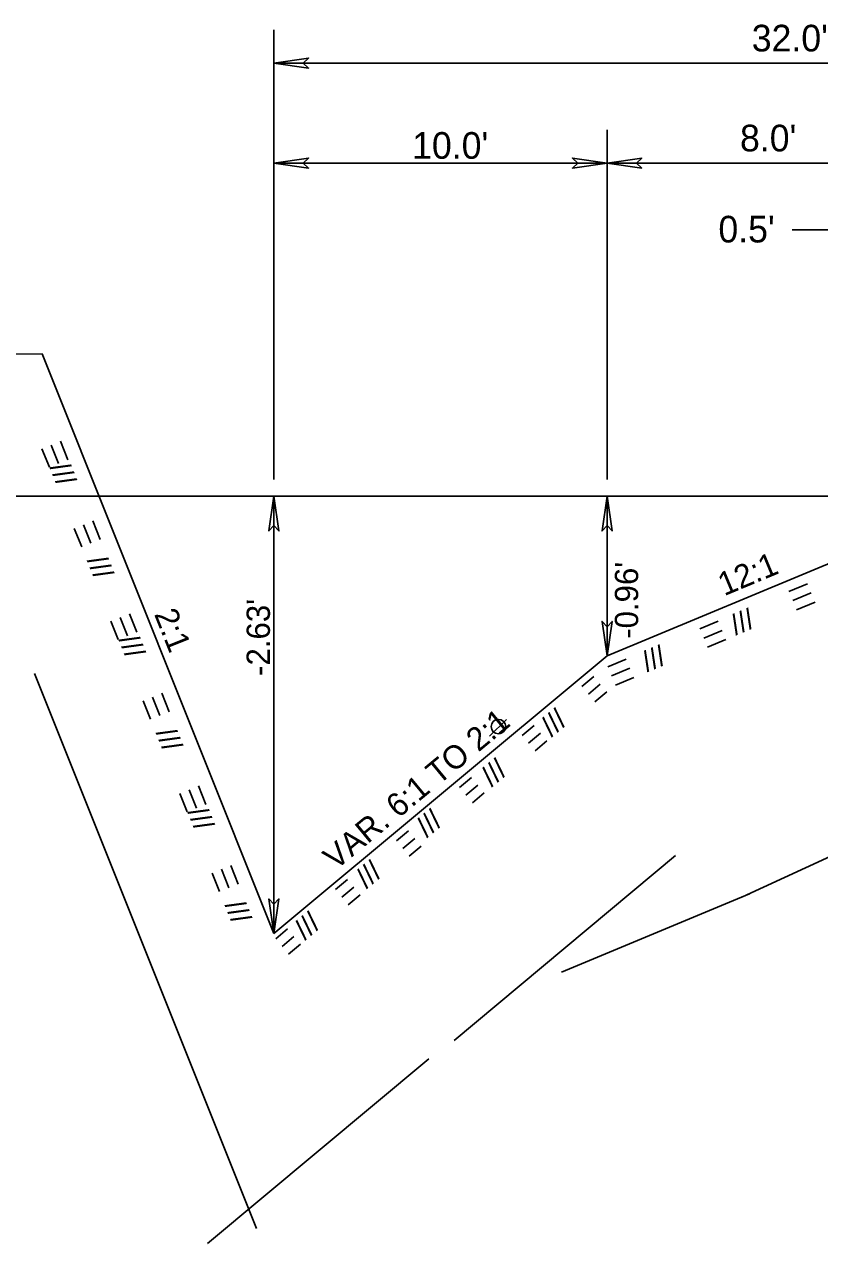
# Model space of a CAD drawing. Extents: x 6561 to 6787, y 19927 to 20919.
# Drawn here: x 6661.57 to 6685.44, y 20846.22 to 20882.81 of the extents above; entities that cross this region are included whole.
import ezdxf

# ---------------------------------------------------------------- set-up
doc = ezdxf.new("R2010")
doc.units = 0
for name, color, linetype in [('Level 1', 7, 'Continuous'), ('Level 11', 7, 'Continuous'), ('Level 7', 7, 'Continuous'), ('Level 8', 7, 'Continuous')]:
    doc.layers.add(name, color=color, linetype=linetype)

msp = doc.modelspace()

# ---------------------------------------------------------------- linework, layer by layer
at = {"layer": 'Level 1'}
for p, q in [((6669.057, 20869.15), (6669.057, 20882.65)), ((6669.057, 20881.65), (6701.057, 20881.65)), ((6679.057, 20879.65), (6679.057, 20869.15)), ((6669.057, 20878.65), (6679.057, 20878.65)), ((6679.057, 20878.65), (6687.022, 20878.65)), ((6684.612, 20876.65), (6686.612, 20876.65)), ((6779.047, 20868.65), (6628.473, 20868.65)), ((6669.057, 20855.525), (6669.057, 20868.65)), ((6679.057, 20863.858), (6679.057, 20868.65))]:
    msp.add_line(p, q, dxfattribs=at)
for points in [[(6669.057, 20881.65), (6670.096, 20881.5), (6669.936, 20881.65), (6670.096, 20881.8)], [(6669.057, 20878.65), (6670.096, 20878.5), (6669.936, 20878.65), (6670.096, 20878.8)], [(6679.057, 20878.65), (6678.018, 20878.8), (6678.178, 20878.65), (6678.018, 20878.5)], [(6679.057, 20878.65), (6680.096, 20878.5), (6679.936, 20878.65), (6680.096, 20878.8)], [(6669.057, 20868.65), (6668.907, 20867.611), (6669.057, 20867.771), (6669.207, 20867.611)], [(6679.057, 20868.65), (6678.907, 20867.611), (6679.057, 20867.771), (6679.207, 20867.611)], [(6679.057, 20863.858), (6679.207, 20864.897), (6679.057, 20864.737), (6678.907, 20864.897)], [(6669.057, 20855.525), (6669.207, 20856.564), (6669.057, 20856.404), (6668.907, 20856.564)]]:
    msp.add_lwpolyline(points, close=True, dxfattribs=at)
at = {"layer": 'Level 11'}
msp.add_line((6629.117, 20872.721), (6662.098, 20872.922), dxfattribs=at)
at = {"layer": 'Level 7'}
for p, q in [((6669.057, 20855.525), (6662.098, 20872.922)), ((6687.057, 20867.192), (6679.057, 20863.858)), ((6679.057, 20863.858), (6669.057, 20855.525)), ((6668.531, 20846.676), (6661.868, 20863.336)), ((6683.125, 20856.629), (6688.218, 20858.984)), ((6681.109, 20857.865), (6674.464, 20852.318)), ((6677.686, 20854.368), (6683.336, 20856.723)), ((6673.708, 20851.767), (6667.063, 20846.22))]:
    msp.add_line(p, q, dxfattribs=at)
for points in [[(6662.318, 20869.52), (6662.095, 20870.077)], [(6662.596, 20869.631), (6662.373, 20870.188)], [(6662.874, 20869.742), (6662.651, 20870.3)], [(6663.845, 20867.352), (6663.623, 20867.909)], [(6663.289, 20867.129), (6663.066, 20867.686)], [(6663.567, 20867.241), (6663.344, 20867.798)], [(6684.514, 20865.795), (6685.068, 20866.026)], [(6684.629, 20865.519), (6685.183, 20865.749)], [(6684.744, 20865.242), (6685.298, 20865.473)], [(6664.665, 20864.459), (6664.442, 20865.016)], [(6664.943, 20864.57), (6664.72, 20865.127)], [(6664.387, 20864.348), (6664.164, 20864.905)], [(6681.841, 20864.672), (6682.395, 20864.902)], [(6681.956, 20864.395), (6682.51, 20864.626)], [(6682.071, 20864.118), (6682.625, 20864.349)], [(6679.075, 20863.534), (6679.629, 20863.765)], [(6679.19, 20863.258), (6679.744, 20863.489)], [(6678.661, 20863.244), (6678.303, 20862.946)], [(6679.305, 20862.981), (6679.859, 20863.212)], [(6678.853, 20863.014), (6678.495, 20862.716)], [(6679.045, 20862.784), (6678.687, 20862.486)], [(6665.358, 20861.957), (6665.135, 20862.514)], [(6665.636, 20862.069), (6665.413, 20862.626)], [(6665.914, 20862.18), (6665.691, 20862.737)], [(6676.869, 20861.766), (6676.511, 20861.468)], [(6677.06, 20861.536), (6676.703, 20861.238)], [(6677.252, 20861.306), (6676.895, 20861.008)], [(6674.988, 20860.206), (6674.63, 20859.908)], [(6666.734, 20859.287), (6666.511, 20859.844)], [(6667.012, 20859.398), (6666.789, 20859.955)], [(6675.18, 20859.976), (6674.822, 20859.678)], [(6666.456, 20859.176), (6666.233, 20859.733)], [(6675.372, 20859.746), (6675.014, 20859.448)], [(6673.094, 20858.61), (6672.736, 20858.311)], [(6673.286, 20858.38), (6672.928, 20858.081)], [(6673.478, 20858.15), (6673.12, 20857.851)], [(6667.427, 20856.785), (6667.204, 20857.342)], [(6667.705, 20856.896), (6667.482, 20857.454)], [(6667.983, 20857.008), (6667.76, 20857.565)], [(6671.261, 20857.146), (6670.903, 20856.847)], [(6671.453, 20856.916), (6671.095, 20856.617)], [(6671.645, 20856.686), (6671.287, 20856.388)], [(6669.468, 20855.668), (6669.11, 20855.369)], [(6669.66, 20855.438), (6669.302, 20855.139)], [(6669.852, 20855.208), (6669.494, 20854.909)]]:
    msp.add_lwpolyline(points, dxfattribs=at)
at = {"layer": 'Level 8'}
msp.add_line((6676.043, 20861.952), (6675.523, 20861.454), dxfattribs=at)
msp.add_circle((6675.796, 20861.738), 0.217, dxfattribs=at)

# ---------------------------------------------------------------- texts
at = {"layer": 'Level 1'}
for s, p in [("32.0'", (6683.399, 20882.002)), ("10.0'", (6673.205, 20878.781)), ("8.0'", (6683.046, 20879.002)), ("0.5'", (6682.398, 20876.268))]:
    msp.add_text(s, height=0.8, dxfattribs=at).set_placement(p)
for s, rotation, p in [('12:1', 22.6199, (6682.571, 20865.649)), ("-0.96'", 90, (6679.99, 20864.373)), ("-2.63'", 90, (6668.938, 20863.259)), ('2:1', 291.8015, (6665.456, 20865.115)), ('VAR. 6:1 TO 2:1', 39.6344, (6670.909, 20857.408))]:
    msp.add_text(s, height=0.7, rotation=rotation, dxfattribs=at).set_placement(p)
at = {"layer": 'Level 7'}
for rotation, p in [(291.8016, (6662.325, 20869.523)), (291.8016, (6663.444, 20866.727)), (22.6195, (6682.918, 20864.475)), (291.8016, (6664.394, 20864.351)), (22.6195, (6680.259, 20863.372)), (39.8519, (6677.389, 20861.412)), (291.8016, (6665.512, 20861.555)), (39.8519, (6675.593, 20859.913)), (291.8016, (6666.463, 20859.179)), (39.8519, (6673.648, 20858.391)), (39.8519, (6671.836, 20856.858)), (291.8016, (6667.581, 20856.383)), (39.8519, (6669.989, 20855.314))]:
    msp.add_text('///', height=0.6, rotation=rotation, dxfattribs=at).set_placement(p)

doc.saveas('drawing.dxf')
